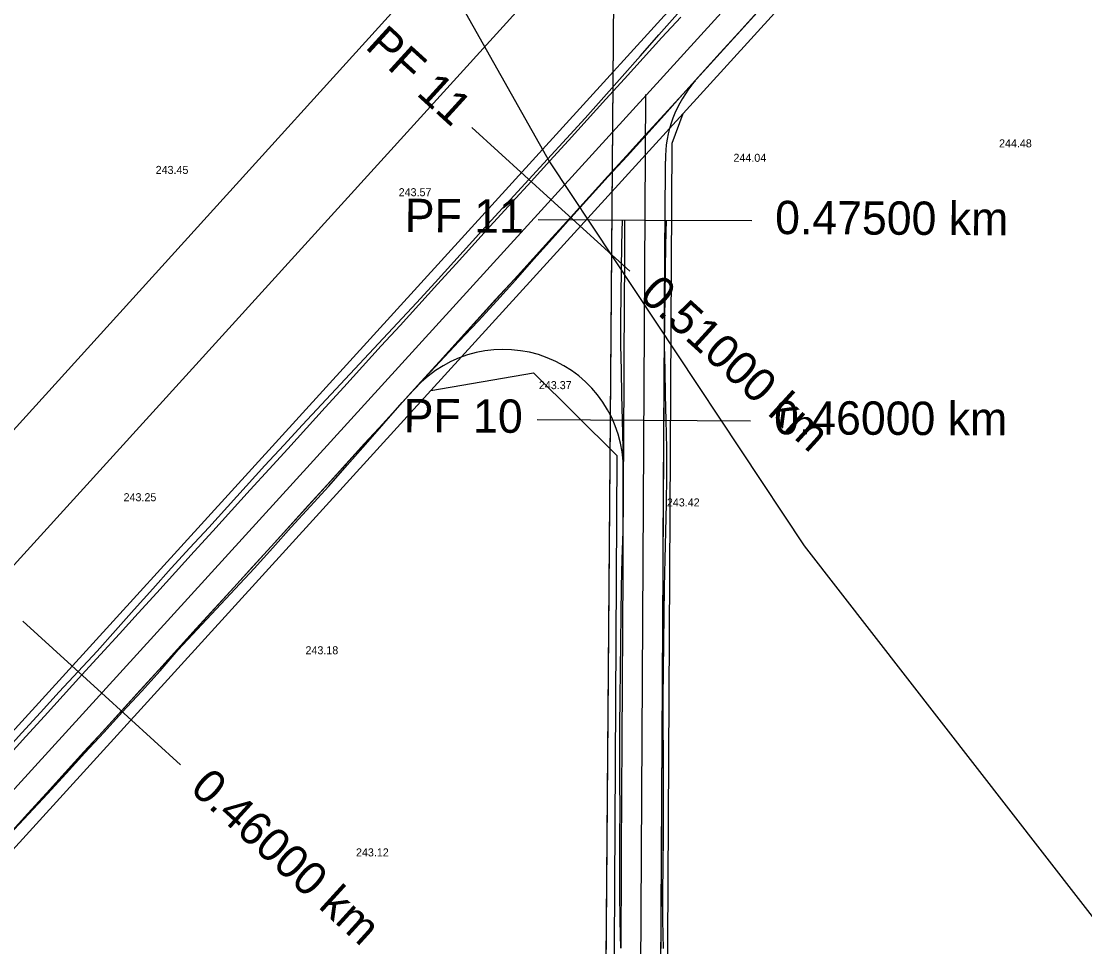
# Model space of a CAD drawing. Extents: x -555887 to -552101, y -1100251 to -1096546.
# Drawn here: x -554581.4 to -554501.7, y -1097271 to -1097201.6 of the extents above; entities that cross this region are included whole.
import ezdxf

# ---------------------------------------------------------------- set-up
doc = ezdxf.new("R2010")
doc.units = 0
for name, color, linetype in [('07_ELEKTRO', 7, 'Continuous'), ('IP_návrh', 7, 'Continuous'), ('PARCELY_cesty', 7, 'Continuous'), ('POLYGONY_rozšíření', 7, 'Continuous'), ('POLYGONY_SITUACE_PF', 7, 'Continuous'), ('POLYGONY_SITUACE_PF_POPISY', 7, 'Continuous'), ('POLYGONY_SITUACE_PO', 7, 'Continuous'), ('vrstevnice', 7, 'Continuous'), ('Výškopis', 7, 'Continuous'), ('ZSST', 7, 'Continuous'), ('zájem', 7, 'Continuous')]:
    doc.layers.add(name, color=color, linetype=linetype)

msp = doc.modelspace()

# ---------------------------------------------------------------- linework, layer by layer
at = {"layer": '07_ELEKTRO'}
msp.add_lwpolyline([(-554536.822, -1097177.881), (-554537.602, -1097278.405), (-554538.021, -1097373.3), (-554538.57, -1097463.608), (-554539.13, -1097565.858), (-554539.536, -1097665.448), (-554540.247, -1097764.017), (-554540.703, -1097863.048), (-554541.185, -1097956.002), (-554541.538, -1098055.43), (-554541.798, -1098155.569), (-554542.001, -1098255.51), (-554542.342, -1098356.724), (-554542.759, -1098456.405)], dxfattribs=at)
at = {"layer": 'IP_návrh'}
msp.add_line((-554875.9, -1097565.92), (-554275.99, -1096905.69), dxfattribs=at)
at = {"layer": 'PARCELY_cesty'}
msp.add_line((-554532.595, -1097210.772), (-554531.76, -1097208.54), dxfattribs=at)
for points in [[(-554879.07, -1097590.15), (-554550.67, -1097229.32), (-554531.76, -1097208.54), (-554275.805, -1096927.303), (-554273.038, -1096923.935), (-554268.632, -1096916.51), (-554265.12, -1096907.97), (-554264.18, -1096901.52)], [(-554875.85, -1097577.71), (-554629.16, -1097306.65), (-554626.42, -1097299.798), (-554612.936, -1097285.133), (-554606.19, -1097281.41), (-554359.61, -1097010.48), (-554356.785, -1097004.211), (-554343.004, -1096989.281), (-554337.66, -1096986.36), (-554280.345, -1096923.377), (-554277.965, -1096920.48), (-554274.105, -1096913.976), (-554271.591, -1096906.676), (-554270.35, -1096901.41)], [(-554512.1, -1097673.16), (-554518.741, -1097666.217), (-554524.725, -1097658.674), (-554527.983, -1097653.272), (-554531.841, -1097644.51), (-554533.518, -1097638.419), (-554534.524, -1097632.144), (-554534.841, -1097625.743), (-554532.595, -1097210.772)], [(-554550.67, -1097229.32), (-554542.97, -1097227.98), (-554536.72, -1097234.2)], [(-554515.01, -1097675.92), (-554521.761, -1097668.847), (-554528.018, -1097660.959), (-554531.54, -1097655.119), (-554535.62, -1097645.854), (-554537.433, -1097639.269), (-554538.509, -1097632.561), (-554538.841, -1097625.831), (-554536.72, -1097234.2)]]:
    msp.add_lwpolyline(points, dxfattribs=at)
at = {"layer": 'POLYGONY_rozšíření'}
for centre, radius, start, end in [((-554524.141, -1097212.04), 8.962, 138.4192, 180.55852), ((-554545.232, -1097235.235), 9, 359.62926, 137.67514)]:
    msp.add_arc(centre, radius, start, end, dxfattribs=at)
at = {"layer": 'POLYGONY_SITUACE_PF'}
for p, q in [((-554547.606, -1097209.61), (-554541.69, -1097214.995)), ((-554541.69, -1097214.995), (-554535.773, -1097220.38)), ((-554542.626, -1097216.494), (-554534.626, -1097216.537)), ((-554534.626, -1097216.537), (-554526.626, -1097216.58)), ((-554542.707, -1097231.494), (-554534.708, -1097231.537)), ((-554534.708, -1097231.537), (-554526.708, -1097231.58)), ((-554581.26, -1097246.589), (-554575.344, -1097251.974)), ((-554575.344, -1097251.974), (-554569.427, -1097257.358))]:
    msp.add_line(p, q, dxfattribs=at)
at = {"layer": 'POLYGONY_SITUACE_PO'}
for p, q in [((-554884.961, -1097592.175), (-554278.075, -1096925.34)), ((-554878.713, -1097588.281), (-554338.286, -1096994.471)), ((-554533.584, -1097202.653), (-554532.202, -1097201.094)), ((-554533.353, -1097202.864), (-554531.951, -1097201.323)), ((-554533.353, -1097202.864), (-554531.951, -1097201.323)), ((-554527.59, -1097202.474), (-554526.188, -1097200.934)), ((-554527.59, -1097202.474), (-554526.188, -1097200.934)), ((-554528.993, -1097204.015), (-554527.59, -1097202.474)), ((-554528.993, -1097204.015), (-554527.59, -1097202.474)), ((-554534.959, -1097204.219), (-554533.584, -1097202.653)), ((-554534.755, -1097204.404), (-554533.353, -1097202.864)), ((-554534.755, -1097204.404), (-554533.353, -1097202.864)), ((-554530.395, -1097205.556), (-554528.993, -1097204.015)), ((-554530.395, -1097205.556), (-554528.993, -1097204.015)), ((-554536.336, -1097205.783), (-554534.959, -1097204.219)), ((-554536.158, -1097205.945), (-554534.755, -1097204.404)), ((-554536.158, -1097205.945), (-554534.755, -1097204.404)), ((-554531.797, -1097207.097), (-554530.395, -1097205.556)), ((-554531.797, -1097207.097), (-554530.395, -1097205.556)), ((-554537.723, -1097207.337), (-554536.336, -1097205.783)), ((-554537.56, -1097207.486), (-554536.158, -1097205.945)), ((-554537.56, -1097207.486), (-554536.158, -1097205.945)), ((-554536.841, -1097625.787), (-554534.575, -1097207.133)), ((-554533.199, -1097208.637), (-554531.797, -1097207.097)), ((-554533.175, -1097208.66), (-554531.797, -1097207.097)), ((-554531.797, -1097207.097), (-554531.797, -1097207.097)), ((-554539.109, -1097208.893), (-554537.723, -1097207.337)), ((-554538.962, -1097209.027), (-554537.56, -1097207.486)), ((-554538.962, -1097209.027), (-554537.56, -1097207.486)), ((-554534.602, -1097210.178), (-554533.199, -1097208.637)), ((-554534.566, -1097210.211), (-554533.175, -1097208.66)), ((-554540.507, -1097210.437), (-554539.109, -1097208.893)), ((-554540.364, -1097210.567), (-554538.962, -1097209.027)), ((-554540.364, -1097210.567), (-554538.962, -1097209.027)), ((-554541.923, -1097211.966), (-554540.507, -1097210.437)), ((-554536.004, -1097211.719), (-554534.602, -1097210.178)), ((-554535.974, -1097211.746), (-554534.566, -1097210.211)), ((-554541.767, -1097212.108), (-554540.364, -1097210.567)), ((-554541.767, -1097212.108), (-554540.364, -1097210.567)), ((-554543.335, -1097213.498), (-554541.923, -1097211.966)), ((-554537.406, -1097213.26), (-554536.004, -1097211.719)), ((-554537.378, -1097213.285), (-554535.974, -1097211.746)), ((-554543.169, -1097213.649), (-554541.767, -1097212.108)), ((-554543.169, -1097213.649), (-554541.767, -1097212.108)), ((-554534.459, -1097462.792), (-554533.102, -1097212.128)), ((-554544.742, -1097215.034), (-554543.335, -1097213.498)), ((-554538.808, -1097214.801), (-554537.406, -1097213.26)), ((-554538.781, -1097214.826), (-554537.378, -1097213.285)), ((-554544.571, -1097215.19), (-554543.169, -1097213.649)), ((-554544.571, -1097215.19), (-554543.169, -1097213.649)), ((-554546.15, -1097216.57), (-554544.742, -1097215.034)), ((-554545.973, -1097216.731), (-554544.571, -1097215.19)), ((-554545.973, -1097216.731), (-554544.571, -1097215.19)), ((-554540.211, -1097216.341), (-554538.808, -1097214.801)), ((-554540.175, -1097216.374), (-554538.781, -1097214.826)), ((-554547.546, -1097218.116), (-554546.15, -1097216.57)), ((-554547.376, -1097218.271), (-554545.973, -1097216.731)), ((-554547.376, -1097218.271), (-554545.973, -1097216.731)), ((-554541.613, -1097217.882), (-554540.211, -1097216.341)), ((-554541.566, -1097217.924), (-554540.175, -1097216.374)), ((-554536.358, -1097218.403), (-554536.307, -1097216.528)), ((-554536.137, -1097218.404), (-554536.126, -1097216.529)), ((-554533.137, -1097218.42), (-554533.126, -1097216.545)), ((-554533.061, -1097218.421), (-554533.012, -1097216.546)), ((-554548.942, -1097219.663), (-554547.546, -1097218.116)), ((-554548.778, -1097219.812), (-554547.376, -1097218.271)), ((-554548.778, -1097219.812), (-554547.376, -1097218.271)), ((-554543.015, -1097219.423), (-554541.613, -1097217.882)), ((-554542.957, -1097219.476), (-554541.566, -1097217.924)), ((-554536.384, -1097220.278), (-554536.358, -1097218.403)), ((-554536.147, -1097220.279), (-554536.137, -1097218.404)), ((-554533.147, -1097220.295), (-554533.137, -1097218.42)), ((-554533.094, -1097220.295), (-554533.061, -1097218.421)), ((-554550.34, -1097221.207), (-554548.942, -1097219.663)), ((-554550.18, -1097221.353), (-554548.778, -1097219.812)), ((-554550.18, -1097221.353), (-554548.778, -1097219.812)), ((-554544.417, -1097220.964), (-554543.015, -1097219.423)), ((-554544.341, -1097221.033), (-554542.957, -1097219.476)), ((-554536.411, -1097222.152), (-554536.384, -1097220.278)), ((-554536.157, -1097222.154), (-554536.147, -1097220.279)), ((-554533.157, -1097222.17), (-554533.147, -1097220.295)), ((-554533.118, -1097222.17), (-554533.094, -1097220.295)), ((-554551.746, -1097222.745), (-554550.34, -1097221.207)), ((-554551.582, -1097222.894), (-554550.18, -1097221.353)), ((-554551.582, -1097222.894), (-554550.18, -1097221.353)), ((-554545.82, -1097222.504), (-554544.417, -1097220.964)), ((-554545.729, -1097222.587), (-554544.341, -1097221.033)), ((-554536.437, -1097224.027), (-554536.411, -1097222.152)), ((-554536.167, -1097224.029), (-554536.157, -1097222.154)), ((-554533.167, -1097224.045), (-554533.157, -1097222.17)), ((-554533.139, -1097224.045), (-554533.118, -1097222.17)), ((-554553.171, -1097224.265), (-554551.746, -1097222.745)), ((-554552.985, -1097224.434), (-554551.582, -1097222.894)), ((-554552.985, -1097224.434), (-554551.582, -1097222.894)), ((-554547.222, -1097224.045), (-554545.82, -1097222.504)), ((-554547.14, -1097224.12), (-554545.729, -1097222.587)), ((-554554.596, -1097225.785), (-554553.171, -1097224.265)), ((-554554.387, -1097225.975), (-554552.985, -1097224.434)), ((-554554.387, -1097225.975), (-554552.985, -1097224.434)), ((-554548.624, -1097225.586), (-554547.222, -1097224.045)), ((-554548.569, -1097225.636), (-554547.14, -1097224.12)), ((-554536.432, -1097225.902), (-554536.437, -1097224.027)), ((-554536.177, -1097225.904), (-554536.167, -1097224.029)), ((-554533.177, -1097225.92), (-554533.167, -1097224.045)), ((-554533.162, -1097225.92), (-554533.139, -1097224.045)), ((-554550.026, -1097227.127), (-554548.624, -1097225.586)), ((-554556.023, -1097227.303), (-554554.596, -1097225.785)), ((-554555.789, -1097227.516), (-554554.387, -1097225.975)), ((-554555.789, -1097227.516), (-554554.387, -1097225.975)), ((-554549.993, -1097227.157), (-554548.569, -1097225.636)), ((-554536.392, -1097227.778), (-554536.432, -1097225.902)), ((-554536.187, -1097227.779), (-554536.177, -1097225.904)), ((-554533.187, -1097227.795), (-554533.177, -1097225.92)), ((-554533.127, -1097227.795), (-554533.162, -1097225.92)), ((-554551.429, -1097228.667), (-554550.026, -1097227.127)), ((-554551.415, -1097228.68), (-554549.993, -1097227.157)), ((-554557.444, -1097228.827), (-554556.023, -1097227.303)), ((-554557.191, -1097229.057), (-554555.789, -1097227.516)), ((-554557.191, -1097229.057), (-554555.789, -1097227.516)), ((-554536.352, -1097229.653), (-554536.392, -1097227.778)), ((-554536.197, -1097229.654), (-554536.187, -1097227.779)), ((-554533.197, -1097229.67), (-554533.187, -1097227.795)), ((-554533.087, -1097229.671), (-554533.127, -1097227.795)), ((-554552.831, -1097230.208), (-554551.429, -1097228.667)), ((-554552.279, -1097229.602), (-554551.415, -1097228.68)), ((-554558.865, -1097230.35), (-554557.444, -1097228.827)), ((-554558.594, -1097230.597), (-554557.191, -1097229.057)), ((-554558.594, -1097230.597), (-554557.191, -1097229.057)), ((-554560.284, -1097231.876), (-554558.865, -1097230.35)), ((-554554.233, -1097231.749), (-554552.831, -1097230.208)), ((-554554.199, -1097231.78), (-554552.822, -1097230.216)), ((-554552.822, -1097230.216), (-554552.279, -1097229.602)), ((-554536.312, -1097231.528), (-554536.352, -1097229.653)), ((-554536.208, -1097231.529), (-554536.197, -1097229.654)), ((-554533.208, -1097231.545), (-554533.197, -1097229.67)), ((-554533.045, -1097231.546), (-554533.087, -1097229.671)), ((-554559.996, -1097232.138), (-554558.594, -1097230.597)), ((-554559.996, -1097232.138), (-554558.594, -1097230.597)), ((-554561.694, -1097233.41), (-554560.284, -1097231.876)), ((-554555.635, -1097233.29), (-554554.233, -1097231.749)), ((-554555.569, -1097233.35), (-554554.199, -1097231.78)), ((-554536.268, -1097233.612), (-554536.312, -1097231.528)), ((-554536.219, -1097233.612), (-554536.208, -1097231.529)), ((-554533.219, -1097233.628), (-554533.208, -1097231.545)), ((-554532.994, -1097233.629), (-554533.045, -1097231.546)), ((-554561.398, -1097233.679), (-554559.996, -1097232.138)), ((-554561.398, -1097233.679), (-554559.996, -1097232.138)), ((-554563.106, -1097234.942), (-554561.694, -1097233.41)), ((-554557.038, -1097234.831), (-554555.635, -1097233.29)), ((-554556.947, -1097234.913), (-554555.569, -1097233.35)), ((-554562.8, -1097235.22), (-554561.398, -1097233.679)), ((-554562.8, -1097235.22), (-554561.398, -1097233.679)), ((-554536.259, -1097235.695), (-554536.268, -1097233.612)), ((-554536.23, -1097235.695), (-554536.219, -1097233.612)), ((-554533.23, -1097235.712), (-554533.219, -1097233.628)), ((-554532.984, -1097235.713), (-554532.994, -1097233.629)), ((-554564.515, -1097236.476), (-554563.106, -1097234.942)), ((-554558.44, -1097236.371), (-554557.038, -1097234.831)), ((-554558.326, -1097236.475), (-554556.947, -1097234.913)), ((-554564.203, -1097236.76), (-554562.8, -1097235.22)), ((-554564.203, -1097236.76), (-554562.8, -1097235.22)), ((-554536.26, -1097237.778), (-554536.259, -1097235.695)), ((-554536.241, -1097237.779), (-554536.23, -1097235.695)), ((-554533.241, -1097237.795), (-554533.23, -1097235.712)), ((-554533.004, -1097237.796), (-554532.984, -1097235.713)), ((-554565.91, -1097238.024), (-554564.515, -1097236.476)), ((-554559.842, -1097237.912), (-554558.44, -1097236.371)), ((-554559.729, -1097238.015), (-554558.326, -1097236.475)), ((-554565.605, -1097238.301), (-554564.203, -1097236.76)), ((-554565.605, -1097238.301), (-554564.203, -1097236.76)), ((-554567.301, -1097239.574), (-554565.91, -1097238.024)), ((-554567.007, -1097239.842), (-554565.605, -1097238.301)), ((-554567.007, -1097239.842), (-554565.605, -1097238.301)), ((-554561.244, -1097239.453), (-554559.842, -1097237.912)), ((-554561.135, -1097239.553), (-554559.729, -1097238.015)), ((-554536.271, -1097239.862), (-554536.26, -1097237.778)), ((-554536.253, -1097239.862), (-554536.241, -1097237.779)), ((-554533.253, -1097239.878), (-554533.241, -1097237.795)), ((-554533.057, -1097239.879), (-554533.004, -1097237.796)), ((-554568.724, -1097241.097), (-554567.301, -1097239.574)), ((-554568.409, -1097241.383), (-554567.007, -1097239.842)), ((-554568.409, -1097241.383), (-554567.007, -1097239.842)), ((-554562.647, -1097240.994), (-554561.244, -1097239.453)), ((-554562.519, -1097241.11), (-554561.135, -1097239.553)), ((-554536.348, -1097241.945), (-554536.271, -1097239.862)), ((-554536.264, -1097241.945), (-554536.253, -1097239.862)), ((-554533.264, -1097241.961), (-554533.253, -1097239.878)), ((-554533.122, -1097241.962), (-554533.057, -1097239.879)), ((-554570.125, -1097242.639), (-554568.724, -1097241.097)), ((-554569.812, -1097242.924), (-554568.409, -1097241.383)), ((-554569.812, -1097242.924), (-554568.409, -1097241.383)), ((-554564.049, -1097242.534), (-554562.647, -1097240.994)), ((-554563.921, -1097242.651), (-554562.519, -1097241.11)), ((-554536.396, -1097244.028), (-554536.348, -1097241.945)), ((-554536.275, -1097244.029), (-554536.264, -1097241.945)), ((-554533.275, -1097244.045), (-554533.264, -1097241.961)), ((-554533.17, -1097244.045), (-554533.122, -1097241.962)), ((-554571.52, -1097244.185), (-554570.125, -1097242.639)), ((-554571.214, -1097244.464), (-554569.812, -1097242.924)), ((-554571.214, -1097244.464), (-554569.812, -1097242.924)), ((-554565.451, -1097244.075), (-554564.049, -1097242.534)), ((-554565.342, -1097244.174), (-554563.921, -1097242.651)), ((-554572.918, -1097245.731), (-554571.52, -1097244.185)), ((-554572.616, -1097246.005), (-554571.214, -1097244.464)), ((-554572.616, -1097246.005), (-554571.214, -1097244.464)), ((-554566.853, -1097245.616), (-554565.451, -1097244.075)), ((-554566.764, -1097245.697), (-554565.342, -1097244.174)), ((-554536.417, -1097246.111), (-554536.396, -1097244.028)), ((-554536.286, -1097246.112), (-554536.275, -1097244.029)), ((-554533.286, -1097246.128), (-554533.275, -1097244.045)), ((-554533.198, -1097246.129), (-554533.17, -1097244.045)), ((-554574.296, -1097247.293), (-554572.918, -1097245.731)), ((-554574.018, -1097247.546), (-554572.616, -1097246.005)), ((-554574.018, -1097247.546), (-554572.616, -1097246.005)), ((-554568.256, -1097247.157), (-554566.853, -1097245.616)), ((-554568.181, -1097247.225), (-554566.764, -1097245.697)), ((-554536.439, -1097248.194), (-554536.417, -1097246.111)), ((-554536.298, -1097248.195), (-554536.286, -1097246.112)), ((-554533.298, -1097248.211), (-554533.286, -1097246.128)), ((-554533.22, -1097248.212), (-554533.198, -1097246.129)), ((-554575.67, -1097248.859), (-554574.296, -1097247.293)), ((-554575.421, -1097249.087), (-554574.018, -1097247.546)), ((-554575.421, -1097249.087), (-554574.018, -1097247.546)), ((-554569.658, -1097248.697), (-554568.256, -1097247.157)), ((-554569.599, -1097248.751), (-554568.181, -1097247.225)), ((-554571.06, -1097250.238), (-554569.658, -1097248.697)), ((-554536.46, -1097250.278), (-554536.439, -1097248.194)), ((-554536.309, -1097250.278), (-554536.298, -1097248.195)), ((-554533.309, -1097250.295), (-554533.298, -1097248.211)), ((-554533.242, -1097250.295), (-554533.22, -1097248.212)), ((-554577.094, -1097250.381), (-554575.67, -1097248.859)), ((-554576.823, -1097250.627), (-554575.421, -1097249.087)), ((-554576.823, -1097250.627), (-554575.421, -1097249.087)), ((-554570.964, -1097250.326), (-554569.599, -1097248.751)), ((-554572.462, -1097251.779), (-554571.06, -1097250.238)), ((-554536.483, -1097252.361), (-554536.46, -1097250.278)), ((-554536.32, -1097252.362), (-554536.309, -1097250.278)), ((-554533.32, -1097252.378), (-554533.309, -1097250.295)), ((-554533.264, -1097252.378), (-554533.242, -1097250.295)), ((-554578.517, -1097251.902), (-554577.094, -1097250.381)), ((-554578.225, -1097252.168), (-554576.823, -1097250.627)), ((-554578.225, -1097252.168), (-554576.823, -1097250.627)), ((-554572.366, -1097251.866), (-554570.964, -1097250.326)), ((-554573.865, -1097253.32), (-554572.462, -1097251.779)), ((-554573.774, -1097253.402), (-554572.366, -1097251.866)), ((-554579.923, -1097253.44), (-554578.517, -1097251.902)), ((-554579.627, -1097253.709), (-554578.225, -1097252.168)), ((-554579.627, -1097253.709), (-554578.225, -1097252.168)), ((-554536.505, -1097254.444), (-554536.483, -1097252.361)), ((-554536.332, -1097254.445), (-554536.32, -1097252.362)), ((-554533.332, -1097254.461), (-554533.32, -1097252.378)), ((-554533.258, -1097254.462), (-554533.264, -1097252.378)), ((-554581.328, -1097254.978), (-554579.923, -1097253.44)), ((-554575.267, -1097254.86), (-554573.865, -1097253.32)), ((-554575.183, -1097254.937), (-554573.774, -1097253.402)), ((-554581.03, -1097255.25), (-554579.627, -1097253.709)), ((-554581.03, -1097255.25), (-554579.627, -1097253.709)), ((-554582.727, -1097256.522), (-554581.328, -1097254.978)), ((-554576.669, -1097256.401), (-554575.267, -1097254.86)), ((-554576.598, -1097256.466), (-554575.183, -1097254.937)), ((-554536.507, -1097256.527), (-554536.505, -1097254.444)), ((-554536.343, -1097256.528), (-554536.332, -1097254.445)), ((-554533.343, -1097256.545), (-554533.332, -1097254.461)), ((-554533.252, -1097256.545), (-554533.258, -1097254.462)), ((-554582.432, -1097256.79), (-554581.03, -1097255.25)), ((-554582.432, -1097256.79), (-554581.03, -1097255.25)), ((-554578.071, -1097257.942), (-554576.669, -1097256.401)), ((-554578.002, -1097258.005), (-554576.598, -1097256.466)), ((-554536.501, -1097258.611), (-554536.507, -1097256.527)), ((-554536.354, -1097258.612), (-554536.343, -1097256.528)), ((-554533.354, -1097258.628), (-554533.343, -1097256.545)), ((-554533.246, -1097258.628), (-554533.252, -1097256.545)), ((-554579.474, -1097259.483), (-554578.071, -1097257.942)), ((-554579.41, -1097259.541), (-554578.002, -1097258.005)), ((-554536.498, -1097260.694), (-554536.501, -1097258.611)), ((-554536.365, -1097260.695), (-554536.354, -1097258.612)), ((-554533.365, -1097260.711), (-554533.354, -1097258.628)), ((-554533.239, -1097260.712), (-554533.246, -1097258.628)), ((-554580.876, -1097261.024), (-554579.474, -1097259.483)), ((-554580.822, -1097261.073), (-554579.41, -1097259.541)), ((-554582.278, -1097262.564), (-554580.876, -1097261.024)), ((-554582.253, -1097262.587), (-554580.822, -1097261.073)), ((-554536.516, -1097262.777), (-554536.498, -1097260.694)), ((-554536.377, -1097262.778), (-554536.365, -1097260.695)), ((-554533.377, -1097262.794), (-554533.365, -1097260.711)), ((-554533.246, -1097262.795), (-554533.239, -1097260.712)), ((-554536.524, -1097264.861), (-554536.516, -1097262.777)), ((-554536.388, -1097264.862), (-554536.377, -1097262.778)), ((-554533.388, -1097264.878), (-554533.377, -1097262.794)), ((-554533.268, -1097264.878), (-554533.246, -1097262.795)), ((-554536.519, -1097266.944), (-554536.524, -1097264.861)), ((-554536.399, -1097266.945), (-554536.388, -1097264.862)), ((-554533.399, -1097266.961), (-554533.388, -1097264.878)), ((-554533.281, -1097266.962), (-554533.268, -1097264.878)), ((-554536.489, -1097269.028), (-554536.519, -1097266.944)), ((-554536.41, -1097269.028), (-554536.399, -1097266.945)), ((-554533.411, -1097269.044), (-554533.399, -1097266.961)), ((-554533.288, -1097269.045), (-554533.281, -1097266.962)), ((-554536.435, -1097271.111), (-554536.489, -1097269.028)), ((-554536.422, -1097271.111), (-554536.41, -1097269.028)), ((-554533.422, -1097271.128), (-554533.411, -1097269.044)), ((-554533.246, -1097271.129), (-554533.288, -1097269.045))]:
    msp.add_line(p, q, dxfattribs=at)
at = {"layer": 'vrstevnice'}
msp.add_lwpolyline([(-554590.892, -1097147.716), (-554577.495, -1097156.634), (-554565.317, -1097170.416), (-554541.771, -1097212.168), (-554522.691, -1097240.948), (-554476.413, -1097300.535), (-554463.016, -1097315.533), (-554439.471, -1097340.26), (-554429.728, -1097354.042)], dxfattribs=at)
at = {"layer": 'ZSST'}
msp.add_lwpolyline([(-554536.822, -1097177.881), (-554537.602, -1097278.405), (-554538.021, -1097373.3), (-554538.57, -1097463.608), (-554539.13, -1097565.858), (-554539.536, -1097665.448), (-554540.247, -1097764.017), (-554540.703, -1097863.048)], dxfattribs=at)
at = {"layer": 'zájem'}
for points in [[(-554333.96, -1096958.92), (-554536.43, -1097182.04), (-554585.15, -1097235.78), (-554588.14, -1097239.01), (-554733.55, -1097399.26)], [(-554733.55, -1097399.26), (-554588.14, -1097239.01), (-554585.15, -1097235.78), (-554536.43, -1097182.04), (-554333.96, -1096958.92)]]:
    msp.add_lwpolyline(points, dxfattribs=at)

# ---------------------------------------------------------------- texts
at = {"layer": 'POLYGONY_SITUACE_PF_POPISY'}
for s, rotation, p in [('PF 11', 317.69467, (-554555.675, -1097203.619)), ('PF 11', 359.68994, (-554552.632, -1097217.44)), ('0.47500 km', 359.68994, (-554524.879, -1097217.59)), ('0.51000 km', 317.69467, (-554535.15, -1097222.299)), ('PF 10', 359.68994, (-554552.713, -1097232.439)), ('0.46000 km', 359.68994, (-554524.96, -1097232.59)), ('0.46000 km', 317.69467, (-554568.804, -1097259.278))]:
    msp.add_text(s, height=2.5, rotation=rotation, dxfattribs=at).set_placement(p)
at = {"layer": 'Výškopis'}
for s, p in [('244.48', (-554508.095, -1097211.09)), ('244.04', (-554527.997, -1097212.17)), ('243.45', (-554571.298, -1097213.08)), ('243.57', (-554553.086, -1097214.75)), ('243.37', (-554542.578, -1097229.21)), ('243.25', (-554573.7, -1097237.61)), ('243.42', (-554532.986, -1097238)), ('243.18', (-554560.068, -1097249.08)), ('243.12', (-554556.284, -1097264.23))]:
    msp.add_text(s, height=0.6, dxfattribs=at).set_placement(p)

doc.saveas('drawing.dxf')
